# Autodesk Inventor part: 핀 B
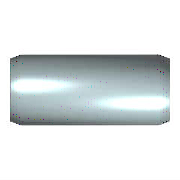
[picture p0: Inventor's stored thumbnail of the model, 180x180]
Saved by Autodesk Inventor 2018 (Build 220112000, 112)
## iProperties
Created: 2012-02
Part Number: 핀 B
Material: 강철, 연강
Description: 평행 핀
Document SubType Name: Modeling
Standard: KS B 1320
Designer: mduedu
Standards Organization: KS
Language: ko-KR
Size Designation: B 4 x  10
Categories: <MemberInstance><Categories><Category DisplayName="조임쇠" InternalName="e4da775c-781d-43d5-af7c-5136215cf5a6" Mnemonic="FSTN"><Category DisplayName="핀" InternalNa
Density: 1 g/cm^3
Appearance: 노란색
IsCustomPart: 1
Author: mduedu
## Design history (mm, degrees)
sketch "스케치"
  geometry: C1 r 2 at (0, 0); 1 further point
  constraints: 1 centre point, 1 coincident
  dimensions: "d1" = 4 diameter of C1 (= NND)
extrude "본체" new body sketch "스케치" distance "d2" = 10 (= NLG); taper "d3" = 0 deg
chamfer "스케치2" distance "d8" = 0.63 (= PHH); stored, may be unused: angle "d9" = 15 deg (= FAWI), second distance "d12" = 0.63 (= PHH)
body "Solid1"
chamfer "모따기1" distance "d4" = 0.63 (= PHH); stored, may be unused: angle "d5" = 15 deg (= FAWI), second distance "d11" = 0.63 (= PHH)
other parameters: "NND" = 4 [user parameter; used in 1 equation term], "NLG" = 10 [user parameter; used in 1 equation term], "PHH" = 0.63 [user parameter; used in 4 equation terms], "FAWI" = 15 deg [user parameter; used in 2 equation terms], "d13" = 0, "d15" = 0, "d16" = 0, "KAH" = 0.5 [user parameter]
